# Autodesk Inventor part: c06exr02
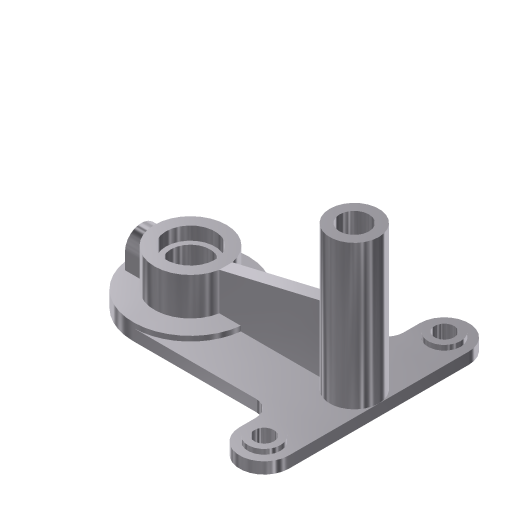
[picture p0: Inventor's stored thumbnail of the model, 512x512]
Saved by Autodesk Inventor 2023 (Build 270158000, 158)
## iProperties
Created: 2001-12
Part Number: c06exr02
Document SubType Name: Modeling
Material: Generic
Density: 1 g/cm^3
Appearance: Metal-AL-6061 (Polished)
Control State: 0
Master: False
Checked Out: False
Shininess: 77.0
Length Units: 11269
Angle Units: 11279
Time Units: 11290
Mass Units: 11283
Length Display Precision: 3
Angle Display Precision: 2
Density: 0.0
Volumn: 0.0
Area: 0.0
PropertySet Name: Model Information
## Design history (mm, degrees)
sketch "Sketch1"
  geometry: L1 (46.121, -53.4)-(46.121, 56.6); L2 (16.121, 56.6)-(16.121, 36.6); L3 (16.121, 36.6)-(-68.879, 36.6); L4 (-68.879, -33.4)-(16.121, -33.4); L5 (16.121, -33.4)-(16.121, -53.4); A1 r 15 centre (31.121, 56.6) between (46.121, 56.6) and (16.121, 56.6); A2 r 35 centre (-68.879, 1.6) between (-68.879, 36.6) and (-68.879, -33.4); A3 r 15 centre (31.121, -53.4) between (16.121, -53.4) and (46.121, -53.4)
  constraints: 10 end point, 6 point on circle, 5 tangent, 3 centre point, 3 parallel, 2 equal length, 1 equal radius, 1 perpendicular, 1 vertical
  dimensions: "d0" = 15 radius of A1; "d1" = 110 distance of L1.start L1.end; "d2" = 100 horizontal distance of A3.centre A2.centre; "d3" = 35 radius of A2
extrude "Extrusion1" new body sketch "Sketch1" distance "d4" = 7; taper "d5" = 0 deg
sketch "Sketch2"
  geometry: C1 r 10 at (31.121, 56.6); C2 r 10 at (31.121, -53.4); C3 r 35 at (-68.879, 1.6); A1 r 35 centre (-68.879, 1.6) between (-68.879, 36.6) and (-68.879, -33.4) reference; A2 r 15 centre (31.121, 56.6) between (46.121, 56.6) and (16.121, 56.6) reference; A3 r 15 centre (31.121, -53.4) between (16.121, -53.4) and (46.121, -53.4) reference
  constraints: 3 centre point, 3 concentric, 2 equal radius
  dimensions: "d45" = 20 diameter of C1
extrude "Extrusion2" join sketch "Sketch2" distance "d6" = 3; taper "d7" = 0 deg
sketch "Sketch3"
  geometry: C1 r 22 at (0, 0); 1 further point
  constraints: 1 centre point, 1 coincident
  dimensions: "d8" = 44 diameter of C1
extrude "Extrusion3" join sketch "Sketch3" distance "d9" = 23; taper "d10" = 0 deg
sketch "Sketch4"
  geometry: L1 (46.121, 56.6)-(46.121, -53.4) reference; L2 (-68.879, 36.6)-(16.121, 36.6) reference; C1 r 15 at (31.121, 1.6)
  constraints: 1 centre point
  dimensions: "d11" = 30 diameter of C1; "d12" = 15 distance from line of L1 C1.centre; "d13" = 35 distance from line of L2 C1.centre
extrude "Extrusion4" join sketch "Sketch4" distance "d14" = 88; taper "d15" = 0 deg
workplane "Work Plane1"
sketch "Sketch5"
  geometry: L1 (22, 33.1)-(85, 48); L2 (0, 7)-(35, 7) reference; L3 (85, 0)-(85, 7) reference; L4 (115, 0)-(115, 7) reference; L5 (115, 0)-(85, 0) reference
  constraints: 2 end point
  dimensions: "d17" = 26.1 distance from line of L2 L1.start; "d18" = 63 distance from line of L3 L1.start; "d19" = 30 distance from line of L4 L1.end; "d20" = 48 distance from line of L5 L1.end
feature "Rib1" sketch "Sketch5" dims "d21" = 1, "d22" = 8
workplane "Work Plane2"
workplane "Work Plane3"
sketch "Sketch7"
  geometry: L1 (10, 0)-(10, 10); L2 (-10, 10)-(-10, 0); L3 (-10, 0)-(10, 0); L4 (55, -10)-(55, -3) reference; A1 r 10 centre (0, 10) between (10, 10) and (-10, 10); 2 further points
  constraints: 6 end point, 2 point on circle, 2 tangent, 1 centre point, 1 parallel, 1 perpendicular, 1 vertical
  dimensions: "d30" = 10 radius of A1; "d34" = 55 distance from line of L4 A1.centre; "d35" = 10 distance of L1.start L1.end
extrude "Extrusion6" join sketch "Sketch7" stored distance "d36" = 88; taper "d37" = 0 deg
sketch "Sketch8"
  geometry: C1 r 10 at (0, 0) reference
hole "Hole1" sketch "Sketch8" at (0, 0) diameter "d38" = 12; stored, may be unused: countersink angle "d42" = 82 deg, drill point angle "d44" = 118 deg; dims "d39" = 6, "d40" = 4, "d41" = 2, "d43" = 8
mirror "Mirror1"
sketch "Sketch9"
  geometry: C1 r 10 at (0, 0)
  constraints: 1 centre point
hole "Hole2" sketch "Sketch9" at (0, 0) diameter "d52" = 18; stored, may be unused: drill point angle "d47" = 118 deg, countersink angle "d48" = 82 deg; dims "d46" = 6, "d49" = 2, "d50" = 4, "d51" = 8
sketch "Sketch10"
  geometry: C1 r 10 at (0, 0)
  constraints: 1 centre point
hole "Hole3" sketch "Sketch10" at (0, 0) diameter "d59" = 24; stored, may be unused: drill point angle "d54" = 118 deg, countersink angle "d55" = 82 deg; dims "d53" = 6, "d56" = 8, "d57" = 30, "d58" = 8
sketch "Sketch11"
  geometry: C1 r 10 at (0, 0)
  constraints: 1 centre point
hole "Hole4" sketch "Sketch11" at (0, 0) diameter "d66" = 10; stored, may be unused: drill point angle "d61" = 0 deg, countersink angle "d62" = 82 deg; dims "d60" = 6, "d63" = 2, "d64" = 4, "d65" = 8
fillet "Fillet1" dims "d67" = 10
body "Solid1"
other parameters: "d16" = -35, "d29" = -8
